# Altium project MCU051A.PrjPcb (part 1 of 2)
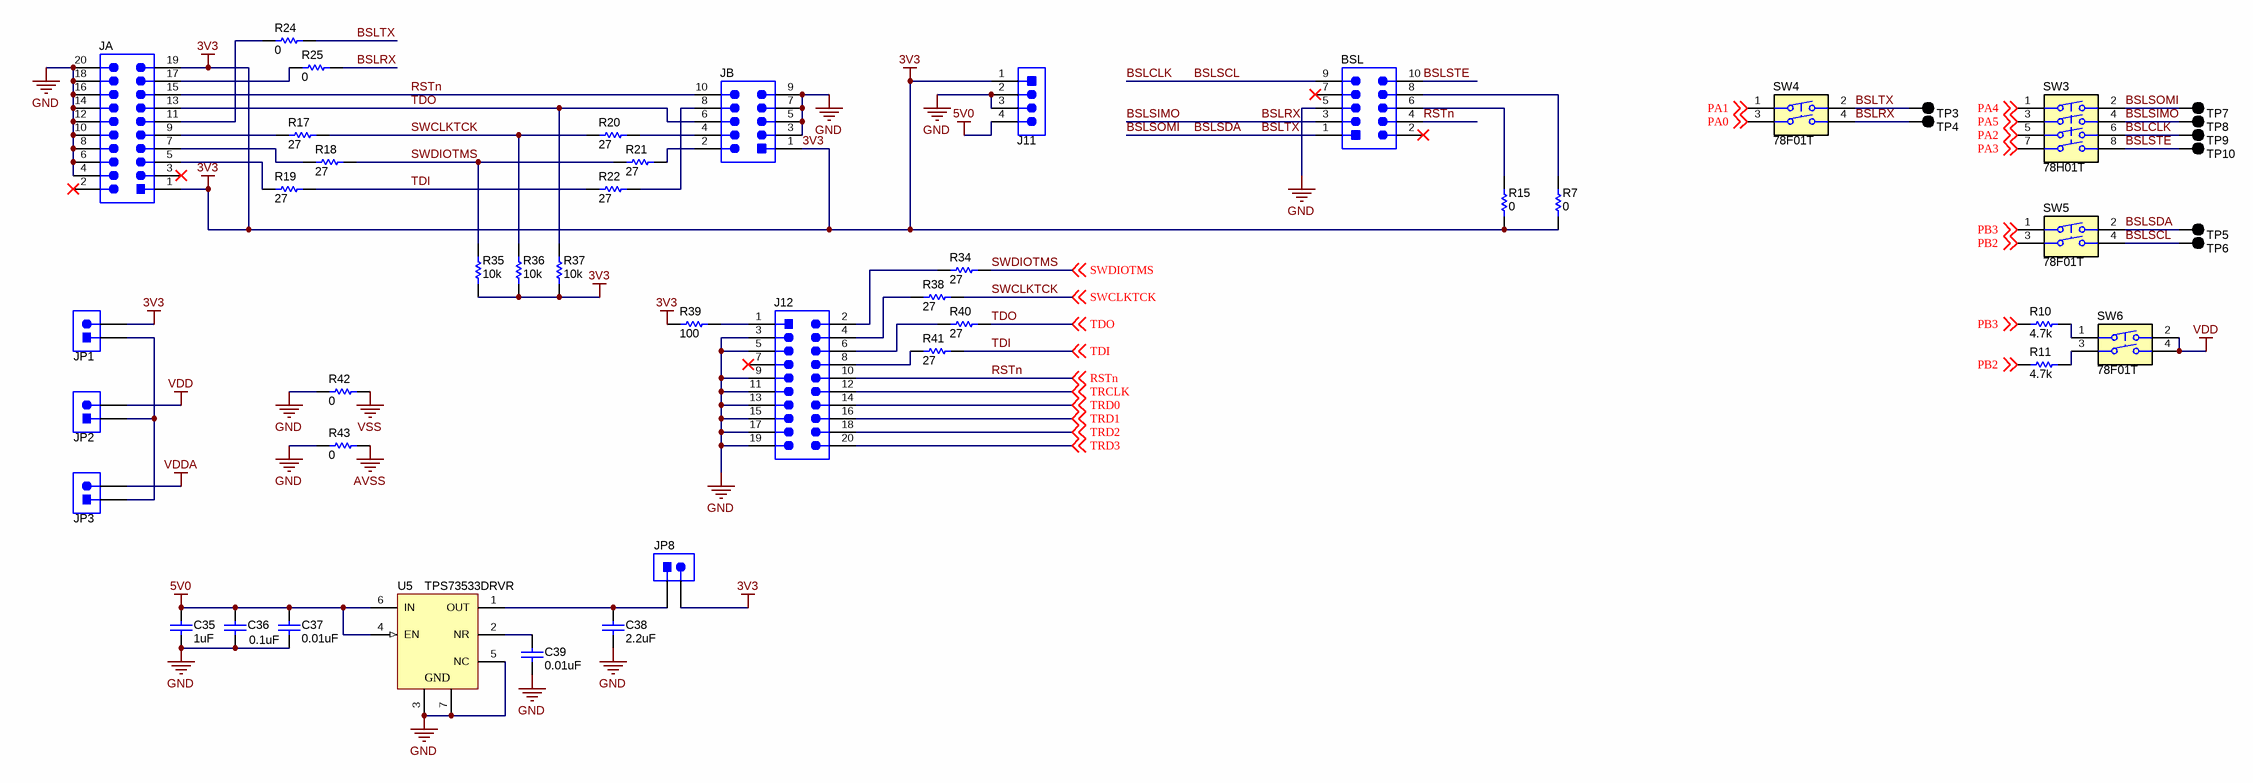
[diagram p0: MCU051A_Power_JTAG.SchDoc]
CopyrightYear: 2018; PCB_Layout: Mike Pridgen; PCB_Rev: A; PRJ_Customer: Public Release; PRJ_Engineer: Mike Pridgen; PRJ_Number: MCU051; PRJ_Title: MSP432E411Y-BGAEVM; SCH_Rev: A; TechSupport: http://www.ti.com/support; TID: N/A
4 sheets, 196 parts. Net scope: global (net labels, ports and power ports of the same name join across sheets).
Board file: MCU051A_PCB.PcbDoc
Sheets:
  MCU051A_Power_JTAG.SchDoc
  MCU051A_MSP432E_Device.SchDoc
  MCU051A_LCD_Memory.SchDoc
  MCU051A_EVM_Hardware.SchDoc

## Sheet MCU051A_Power_JTAG.SchDoc
size 431 x 279 mm; Date: Not shown in title block; ApprovedBy: Not shown in title block; CheckedBy: Not shown in title block; Author: Not shown in title block; CompanyName: Not shown in title block; Engineer: Not shown in title block; Organization: Not shown in title block; Address1: Not shown in title block; Address2: Not shown in title block; Address3: Not shown in title block; Address4: Not shown in title block; DocumentNumber: 1; Revision: Use project parameter SCH_Rev; SheetNumber: 1; SheetTotal: 4; PageSetup: Record=PageOptions¦CenterHorizontal=True¦CenterVertical=True¦PrintScale=1.00¦XCorrection=1.00¦YCorrection=1.00¦PrintKind=0¦BorderSize=5000000¦LeftOffset=0¦BottomOffset=0¦Orientation=2¦PaperLength=1000¦PaperWidth=1000¦Scale=100¦PaperSource=15¦PrintQuality=600¦MediaType=1¦DitherType=10¦PaperKind=Letter¦PrintScaleMode=1

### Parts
BSL  AWHW-10G-0202-T  [Assman_AWHW-10G-0x02-T]  (value not drawn)
C35  ValueDisplayed: 1uF  [0603]  (hidden comment: GRM188R71A105KA61D)
C36  ValueDisplayed: 0.1uF  [0603]  (hidden comment: GRM188R71C104KA01D)
C37  ValueDisplayed: 0.01uF  [0603]  (hidden comment: GRM188R71C103KA01D)
C38  ValueDisplayed: 2.2uF  [0603]  (hidden comment: GRM188Z71C225KE43)
C39  ValueDisplayed: 0.01uF  [0603]  (hidden comment: GRM188R71C103KA01D)
J11  TSW-104-07-T-S  [Samtec_TSW-104-07-T-S]  (value not drawn)
J12  FTSH-110-01-L-DV-K  [Samtec_FTSH-110-01-x-DV-K]  (value not drawn)
JA  5103309-5  [CONN_5103309-5]  (value not drawn)
JB  FTSH-105-01-F-D-K  [Samtec_FTSH-105-01-x-D-K]  (value not drawn)
JP1  HMTSW-102-07-G-S-240  [SAMTEC_HMTSW-102-07-G-S-240]  (value not drawn)
JP2  HMTSW-102-07-G-S-240  [SAMTEC_HMTSW-102-07-G-S-240]  (value not drawn)
JP3  HMTSW-102-07-G-S-240  [SAMTEC_HMTSW-102-07-G-S-240]  (value not drawn)
JP8  HMTSW-102-07-G-S-240  [SAMTEC_HMTSW-102-07-G-S-240]  (value not drawn)
R7  ValueDisplayed: 0  [0805_HV]  (hidden comment: RC0805JR-070RL)
R10  ValueDisplayed: 4.7k  [0805_HV]  (hidden comment: CRCW08054K70JNEA)
R11  ValueDisplayed: 4.7k  [0805_HV]  (hidden comment: CRCW08054K70JNEA)
R15  ValueDisplayed: 0  [0805_HV]  (hidden comment: RC0805JR-070RL)
R17  ValueDisplayed: 27  [0805_HV]  (hidden comment: CRCW080527R0JNEA)
R18  ValueDisplayed: 27  [0805_HV]  (hidden comment: CRCW080527R0JNEA)
R19  ValueDisplayed: 27  [0805_HV]  (hidden comment: CRCW080527R0JNEA)
R20  ValueDisplayed: 27  [0805_HV]  (hidden comment: CRCW080527R0JNEA)
R21  ValueDisplayed: 27  [0805_HV]  (hidden comment: CRCW080527R0JNEA)
R22  ValueDisplayed: 27  [0805_HV]  (hidden comment: CRCW080527R0JNEA)
R24  ValueDisplayed: 0  [0805_HV]  (hidden comment: RC0805JR-070RL)
R25  ValueDisplayed: 0  [0805_HV]  (hidden comment: RC0805JR-070RL)
R34  ValueDisplayed: 27  [0805_HV]  (hidden comment: CRCW080527R0JNEA)
R35  ValueDisplayed: 10k  [0603]  (hidden comment: RC1608J103CS)
R36  ValueDisplayed: 10k  [0603]  (hidden comment: RC1608J103CS)
R37  ValueDisplayed: 10k  [0603]  (hidden comment: RC1608J103CS)
R38  ValueDisplayed: 27  [0805_HV]  (hidden comment: CRCW080527R0JNEA)
R39  ValueDisplayed: 100  [0603]  (hidden comment: RC0603FR-07100RL)
R40  ValueDisplayed: 27  [0805_HV]  (hidden comment: CRCW080527R0JNEA)
R41  ValueDisplayed: 27  [0805_HV]  (hidden comment: CRCW080527R0JNEA)
R42  ValueDisplayed: 0  [0805_HV]  (hidden comment: CRCW08050000Z0EA)
R43  ValueDisplayed: 0  [0805_HV]  (hidden comment: CRCW08050000Z0EA)
SW3  78H01T  [SW_78H01T]
SW4  78F01T  [SW_78F01T]
SW5  78F01T  [SW_78F01T]
SW6  78F01T  [SW_78F01T]
TP3  5001  [Keystone5001]  (value not drawn)
TP4  5001  [Keystone5001]  (value not drawn)
TP5  5001  [Keystone5001]  (value not drawn)
TP6  5001  [Keystone5001]  (value not drawn)
TP7  5001  [Keystone5001]  (value not drawn)
TP8  5001  [Keystone5001]  (value not drawn)
TP9  5001  [Keystone5001]  (value not drawn)
TP10  5001  [Keystone5001]  (value not drawn)
U5  TPS73533DRVR  [DRV0006A]

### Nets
3V3: J11.1 JA.1 JA.19 JB.1 JP1.2 JP8.2 R7.1 R15.1 R35.1 R36.1 R37.1 R39.1
5V0: C35.1 C36.1 C37.1 J11.4 U5.4(EN) U5.6(IN)
AVSS: R43.2
GND: BSL.5 C35.2 C36.2 C37.2 C38.2 C39.2 J11.2 J11.3 J12.3 J12.5 J12.9 J12.11 J12.13 J12.15 J12.17 J12.19 JA.4 JA.6 JA.8 JA.10 JA.12 JA.14 JA.16 JA.18 JA.20 JB.3 JB.5 JB.7 JB.9 R42.1 R43.1 U5.3(GND) U5.5(NC) U5.7(GND)
VDD: JP2.2 SW6.2 SW6.4
VDDA: JP3.2
VSS: R42.2
BSLCLK: BSL.9 SW3.6 SW5.4 TP6.1 TP9.1  [also labelled BSLSCL]
BSLRX: BSL.3 R25.2 SW3.4 SW4.4 TP4.1 TP8.1  [also labelled BSLSIMO]
BSLSDA: BSL.1 R24.2 SW3.2 SW4.2 SW5.2 TP3.1 TP5.1 TP7.1  [also labelled BSLSOMI, BSLTX]
BSLSTE: BSL.10 SW3.8 TP10.1
PA0: SW4.3 ; off-sheet PA0
PA1: SW4.1 ; off-sheet PA1
PA2: SW3.5 ; off-sheet PA2
PA3: SW3.7 ; off-sheet PA3
PA4: SW3.1 ; off-sheet PA4
PA5: SW3.3 ; off-sheet PA5
PB2: R11.1 SW5.3 ; off-sheet PB2
PB3: R10.1 SW5.1 ; off-sheet PB3
RSTn: BSL.4 J12.10 JA.15 JB.10 ; off-sheet RSTn
SWCLKTCK: R17.2 R20.1 R36.2 R38.2 ; off-sheet SWCLKTCK  [project net PC0]
SWDIOTMS: R18.2 R21.1 R34.2 R35.2 ; off-sheet SWDIOTMS  [project net PC1]
TDI: R19.2 R22.1 R41.2 ; off-sheet TDI  [project net PC2]
TDO: JA.13 JB.6 R37.2 R40.2 ; off-sheet TDO  [project net PC3]
TRCLK: J12.12 ; off-sheet TRCLK  [project net PF3]
TRD0: J12.14 ; off-sheet TRD0  [project net PF2]
TRD1: J12.16 ; off-sheet TRD1  [project net PF1]
TRD2: J12.18 ; off-sheet TRD2  [project net PF0]
TRD3: J12.20 ; off-sheet TRD3  [project net PF4]
NetBSL_6: BSL.6 R15.2
NetBSL_8: BSL.8 R7.2
NetC38_1: C38.1 JP8.1 U5.1(OUT)
NetC39_1: C39.1 U5.2(NR)
NetJ12_1: J12.1 R39.2
NetJ12_2: J12.2 R34.1
NetJ12_4: J12.4 R38.1
NetJ12_6: J12.6 R40.1
NetJ12_8: J12.8 R41.1
NetJA_5: JA.5 R19.1
NetJA_7: JA.7 R18.1
NetJA_9: JA.9 R17.1
NetJA_11: JA.11 R24.1
NetJA_17: JA.17 R25.1
NetJB_2: JB.2 R21.2
NetJB_4: JB.4 R20.2
NetJB_8: JB.8 R22.2
NetJP1_1: JP1.1 JP2.1 JP3.1
NetR10_2: R10.2 SW6.1
NetR11_2: R11.2 SW6.3

Not connected (* = marked no-connect by the designer): BSL 2* 7*; J12 7*; JA 2* 3*

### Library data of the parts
BSL = CMP-0075161-1: Header(Shrouded), 2.54mm, 5x2, Gold, TH; Manufacturer: Assman WSW; CNHeader: False; Green_Lifecycle: Active; Shrouded: Y; Gender: Male; Green_REACh: Passed; Row_Count: 2; RowSpacing_mm: 2.54
C35 = CMP-0007365-4: CAP, CERM, 1 uF, 10 V, +/- 10%, X7R, 0603; Manufacturer: MuRata; TaMin_C: -55°C; ESR_ohm: 0.011; Polarized: N; SizeAreaWB_mm2: 4.68; Value1: 0.011 ohm; U/M: EA; Value: 1uF; TaMax_C: 125°C; SizeZ_mm: 1; SizeX_mm: 1.6; SizeY_mm: 0.8; Value2: 10V; SizeArea_mm2: 1.28; CompType: Capacitor; Cap_F: 1µF; AEC Category: Q200
C36 = CMP-0007378-5: CAP, CERM, 0.1 uF, 16 V, +/- 10%, X7R, 0603; Manufacturer: MuRata; TaMin_C: -55°C; Polarized: N; SizeAreaWB_mm2: 4.68; Value1: Unknown; U/M: EA; Value: 0.1uF; TaMax_C: 125°C; SizeZ_mm: 1; SizeX_mm: 1.6; SizeY_mm: 0.8; Value2: 16V; SizeArea_mm2: 1.28; CompType: Capacitor; Cap_F: 100nF; AEC Category: Q200
C37 C39 = CMP-0007377-4: CAP, CERM, 0.01 uF, 16 V, +/- 10%, X7R, 0603; Manufacturer: MuRata; TaMin_C: -55°C; Polarized: N; SizeAreaWB_mm2: 4.68; Value1: Unknown; U/M: EA; Value: 0.01uF; TaMax_C: 125°C; SizeZ_mm: 1; SizeX_mm: 1.6; Value2: 16V; SizeArea_mm2: 1.28; CompType: Capacitor; Cap_F: 10nF; AEC Category: Q200; SizeY_mm: 0.8
C38 = CMP-0007499-4: CAP, CERM, 2.2 uF, 16 V, +/- 10%, X7R, 0603; Manufacturer: MuRata; TaMin_C: -55°C; Polarized: N; SizeAreaWB_mm2: 4.68; Value1: Unknown; U/M: EA; Value: 2.2uF; TaMax_C: 125°C; SizeZ_mm: 1; SizeX_mm: 1.6; SizeY_mm: 0.8; Value2: 16V; SizeArea_mm2: 1.28; AEC Category: Q200; Cap_F: 2.2µF
J11 = CMP-0078238-2: Header, 2.54mm, 4x1, Tin, TH; Manufacturer: Samtec; Pitch_mm: 2.54; Gender: Male; Cert_UL: Y; Shrouded: N; Row_Count: 1
J12 = CMP-0075631-1: Header (Shrouded), 1.27mm, 10x2, Tin, SMT; Manufacturer: Samtec; Pitch_mm: 1.27; Gender: Male; Cert_CSA: Y; Current_A: 3.3A; CT: False; Row_Count: 2
JA = CMP-0054842-1: Header (shrouded), 100mil, 10x2,  Gold, TH; Manufacturer: TE Connectivity; CNHeader: FALSE; Green_Lifecycle: Active; Green_REACh: Passed
JB = CMP-0075533-1: Header, 1.27 mm, 5x2, Gold, TH; Manufacturer: Samtec; Pitch_mm: 1.27; Gender: Male; Green_REACh: Passed; CT: False; Shrouded: Y; Green_Lifecycle: Active; Row_Count: 2
JP1-JP3 JP8 = CMP-0075500-1: Header, 100mil, 2x1, Gold, TH; Manufacturer: Samtec; Green_REACh: Passed; CT: False; Green_Lifecycle: Active; CNHeader: True
R7 R15 R24 R25 = CMP-0020803-2: RES, 0, 5%, 0.125 W, 0805; Manufacturer: Yageo America; Power_W: 125mW; TempCo: 200 ppm/C; Value_Code: 0000; U/M: EA; Value: 0; EIA_Code: E24; SizeX_mm: 2; SizeY_mm: 1.25; SizeZ_mm: 1.45; Value2: 0.125W; SizeArea_mm2: 2.5; CompType: Resistor; VDC_V: 150V; AEC Category: Q200
R10 R11 = CMP-0020559-3: RES, 4.7 k, 5%, 0.125 W, AEC-Q200 Grade 0, 0805; Manufacturer: Vishay-Dale; Power_W: 125mW; TempCo: 200 ppm/C; Value_Code: 4k70; Value: 4.7k; EIA_Code: E24; SizeX_mm: 2; SizeY_mm: 1.25; SizeZ_mm: 1.45; Value2: 0.125W; SizeArea_mm2: 2.5; CompType: Resistor; AEC Qualified: Y; VDC_V: 150V; AEC Category: Q200; AEC Grade: 0
R17-R22 R34 R38 R40 R41 = CMP-0020509-3: RES, 27, 5%, 0.125 W, AEC-Q200 Grade 0, 0805; Manufacturer: Vishay-Dale; Power_W: 125mW; TempCo: 200 ppm/C; Value_Code: 27R0; Value: 27; EIA_Code: E24; SizeX_mm: 2; SizeY_mm: 1.25; SizeZ_mm: 1.45; Value2: 0.125W; SizeArea_mm2: 2.5; CompType: Resistor; AEC Qualified: Y; VDC_V: 150V; AEC Category: Q200; AEC Grade: 0
R35-R37 = CMP-0025945-3: RES, 10 k, 5%, 0.1 W, 0603; Manufacturer: Samsung Electro-Mechanics; Power_W: 100mW; TempCo: 100 ppm/C; Value_Code: 10k0; U/M: EA; Value: 10k; EIA_Code: E24; SizeX_mm: 1.6; SizeY_mm: 0.8; SizeZ_mm: 1; Value2: 0.1W; SizeArea_mm2: 1.28; AEC Qualified: N; VDC_V: 31V; AEC Category: Q200
R39 = CMP-0022736-2: RES, 100, 1%, 0.1 W, 0603; Manufacturer: Yageo America; Power_W: 100mW; TempCo: 200 ppm/C; Value_Code: 100R; U/M: EA; Value: 100; EIA_Code: E96; SizeX_mm: 1.6; SizeY_mm: 0.8; SizeZ_mm: 1; Value2: 0.1W; SizeArea_mm2: 1.28; VDC_V: 150V; AEC Category: Q200
R42 R43 = CMP-0020442-3: RES, 0, 5%, 0.125 W, AEC-Q200 Grade 0, 0805; Manufacturer: Vishay-Dale; Power_W: 125mW; TempCo: 200 ppm/C; Value_Code: 0000; Value: 0; EIA_Code: E24; SizeX_mm: 2; SizeY_mm: 1.25; SizeZ_mm: 1.45; Value2: 0.125W; SizeArea_mm2: 2.5; AEC Qualified: Y; VDC_V: 150V; AEC Category: Q200
SW3 = CMP-0002271-1: Switch, 4PST, Slide, Off-On, 1 Pos, 0.15A, 30V, TH; Manufacturer: Grayhill; CurrentRating_mA: 150A; PositionCount: 1
SW4-SW6 = CMP-0002270-1: Switch, DPST, Slide, Off-On, 1 Pos, 0.15A, 30V, TH; Manufacturer: Grayhill; CurrentRating_mA: 150A; PositionCount: 1
TP3-TP10 = CMP-0055138-1: Test Point, Miniature, Black, TH; Manufacturer: Keystone; CNHeader: FALSE; Green_Lifecycle: Active; Green_REACh: Passed; ContactFinish: Silver; CT: TRUE
U5 = CMP-0036330-5: Single Output High PSRR LDO, 500 mA, Fixed 3.3 V Output, 2.7 to 6.5 V Input, with Low IQ, 6-pin SON (DRV), -40 to 125 degC, Green (RoHS & no Sb/Br); Manufacturer: Texas Instruments; SubFamily: Single Channel LDO; Vin(Max)(V): 6.5; Vin(Min)(V): 2.7; Iout(Max)(A): 0.5; Iq(Typ)(mA): 0.04; Fixed Output Options(V): 3.3; Vdo(Typ)(mV): 280; Accuracy(%): 2; CompType: IC; SizeAreaWB_mm2: 9; SizeArea_mm2: 4; SizeZ_mm: 0.8

## Sheet MCU051A_MSP432E_Device.SchDoc
size 431 x 279 mm; Date: Not shown in title block; ApprovedBy: Not shown in title block; CheckedBy: Not shown in title block; Author: Not shown in title block; CompanyName: Not shown in title block; Engineer: Not shown in title block; Organization: Not shown in title block; Address1: Not shown in title block; Address2: Not shown in title block; Address3: Not shown in title block; Address4: Not shown in title block; DocumentNumber: 1; Revision: Use project parameter SCH_Rev; SheetNumber: 2; SheetTotal: 4; PageSetup: Record=PageOptions¦CenterHorizontal=True¦CenterVertical=True¦PrintScale=1.00¦XCorrection=1.00¦YCorrection=1.00¦PrintKind=0¦BorderSize=5000000¦LeftOffset=0¦BottomOffset=0¦Orientation=2¦PaperLength=1000¦PaperWidth=1000¦Scale=100¦PaperSource=15¦PrintQuality=600¦MediaType=1¦DitherType=10¦PaperKind=Letter¦PrintScaleMode=1
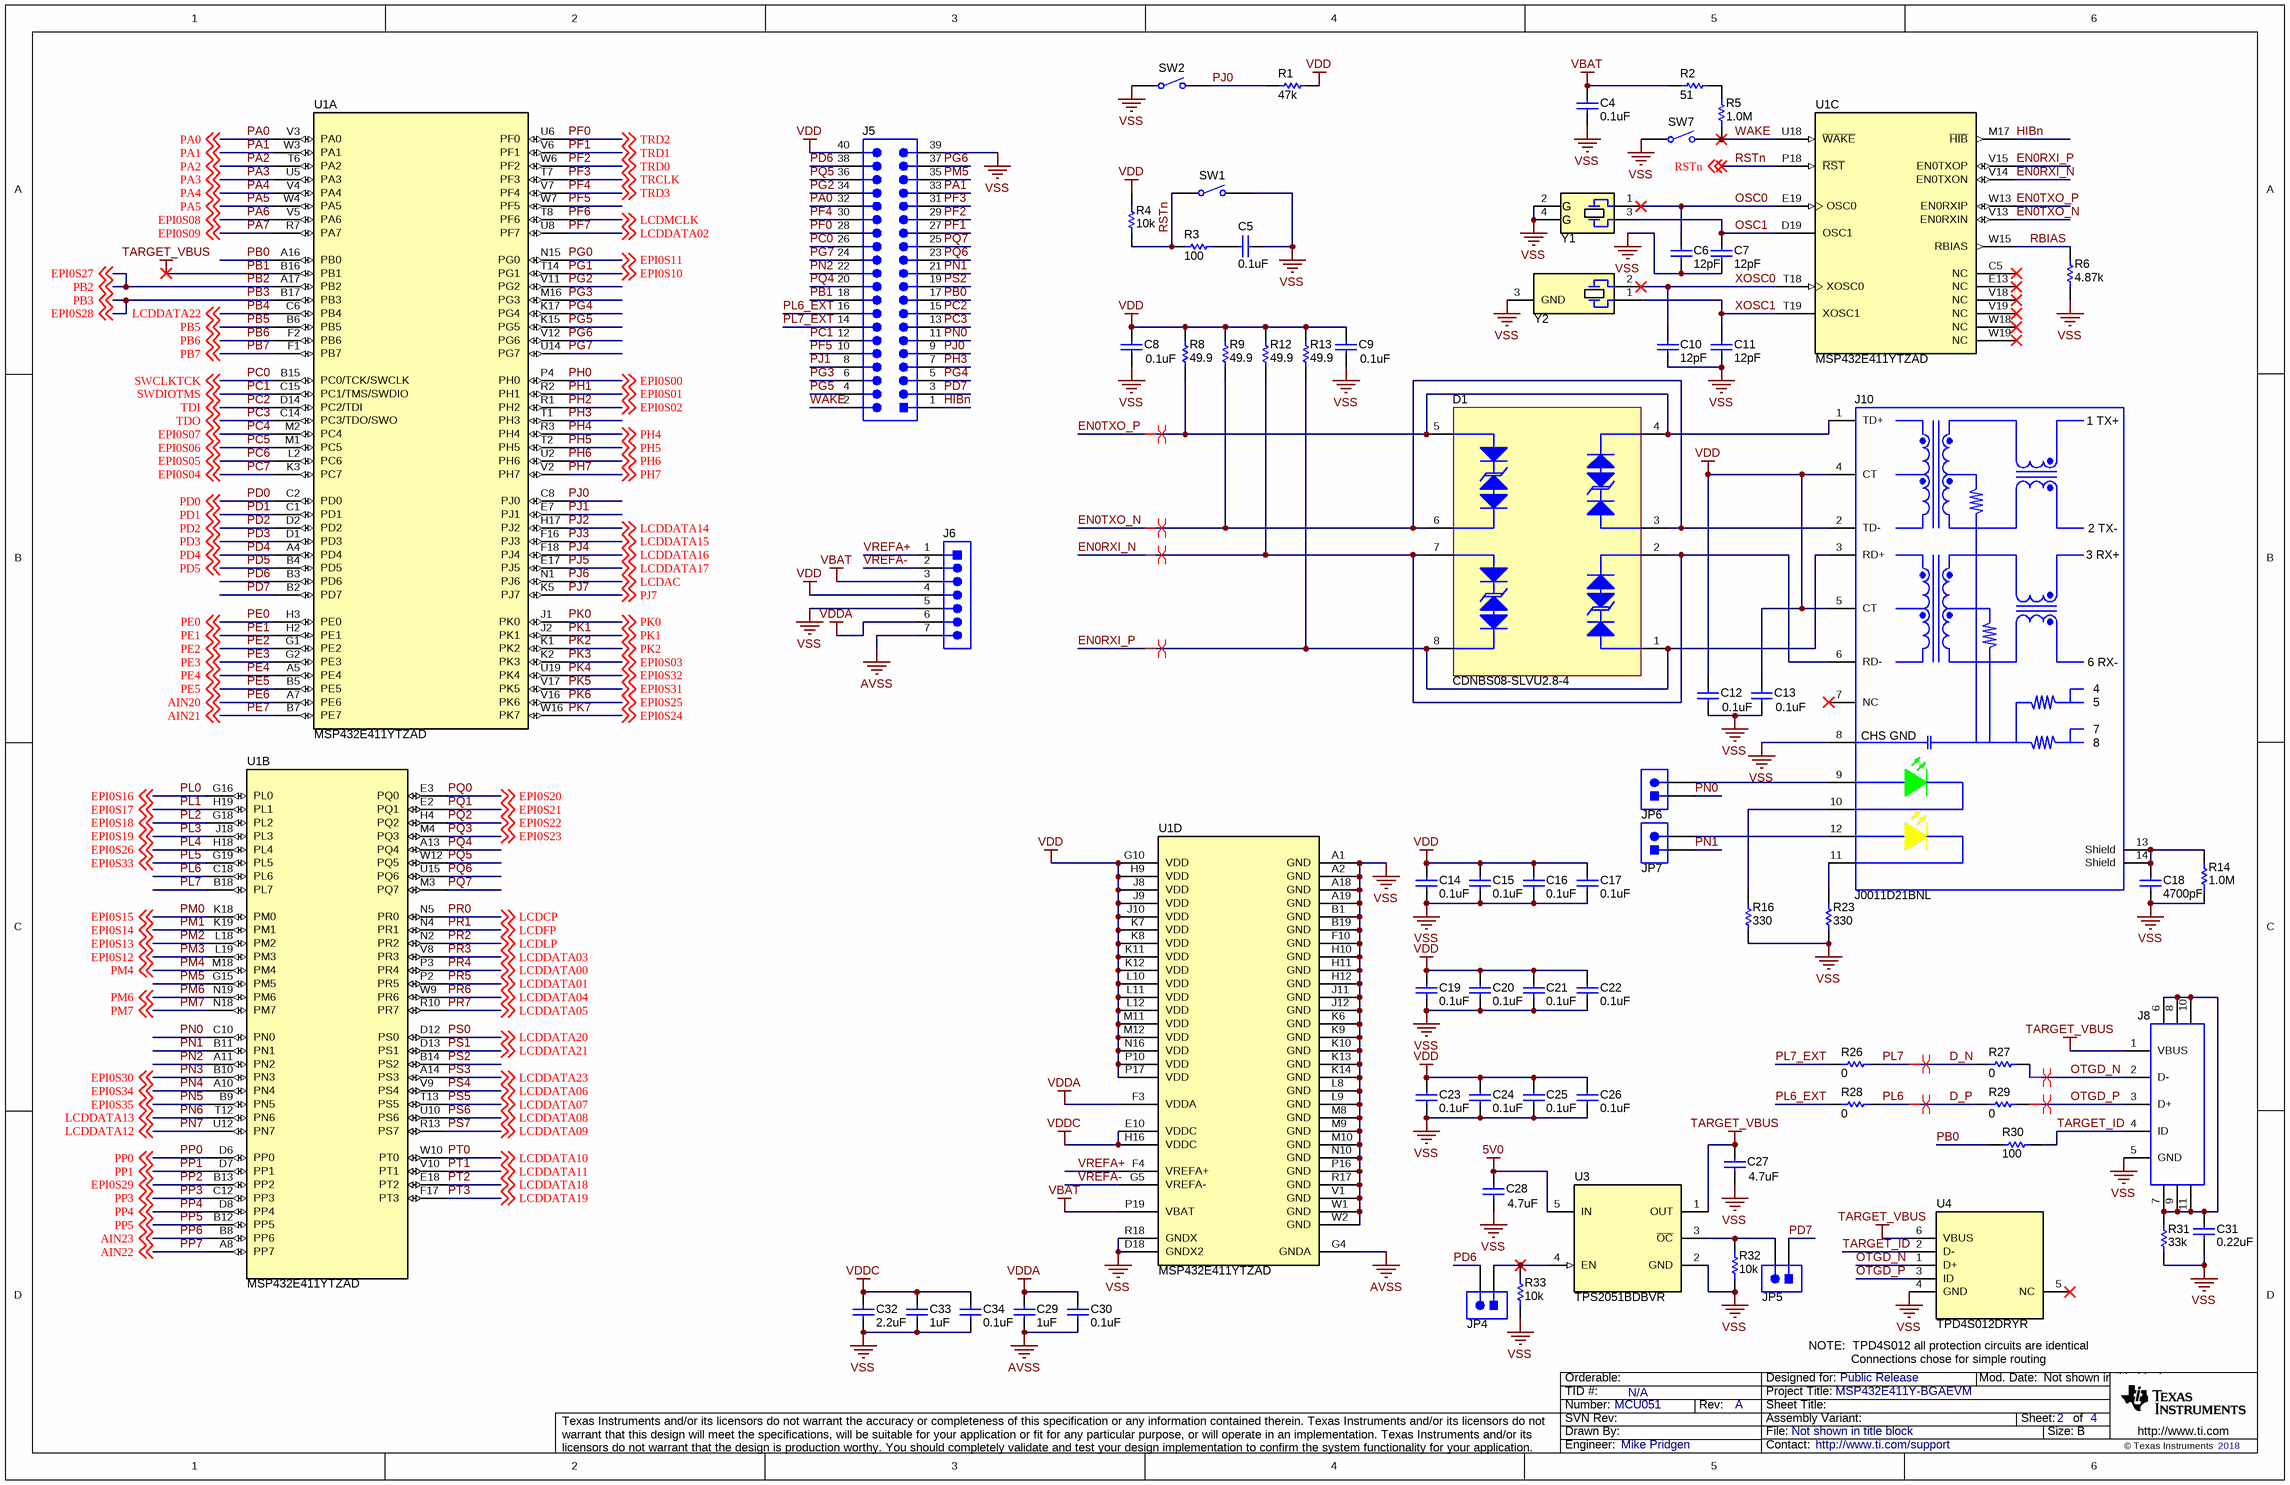
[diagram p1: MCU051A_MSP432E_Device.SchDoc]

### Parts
C4  ValueDisplayed: 0.1uF  [0603]  (hidden comment: GRM188R71C104KA01D)
C5  ValueDisplayed: 0.1uF  [0805_HV]  (hidden comment: C0805C104K4RACTU)
C6  ValueDisplayed: 12pF  [0603]  (hidden comment: GRM1885C1H120JA01D)
C7  ValueDisplayed: 12pF  [0603]  (hidden comment: GRM1885C1H120JA01D)
C8  ValueDisplayed: 0.1uF  [0603]  (hidden comment: GRM188R71C104KA01D)
C9  ValueDisplayed: 0.1uF  [0603]  (hidden comment: GRM188R71C104KA01D)
C10  ValueDisplayed: 12pF  [0603]  (hidden comment: GRM1885C1H120JA01D)
C11  ValueDisplayed: 12pF  [0603]  (hidden comment: GRM1885C1H120JA01D)
C12  ValueDisplayed: 0.1uF  [0603]  (hidden comment: GRM188R71C104KA01D)
C13  ValueDisplayed: 0.1uF  [0603]  (hidden comment: GRM188R71C104KA01D)
C14  ValueDisplayed: 0.1uF  [0402]  (hidden comment: GRM155R71A104KA01D)
C15  ValueDisplayed: 0.1uF  [0402]  (hidden comment: GRM155R71A104KA01D)
C16  ValueDisplayed: 0.1uF  [0402]  (hidden comment: GRM155R71A104KA01D)
C17  ValueDisplayed: 0.1uF  [0402]  (hidden comment: GRM155R71A104KA01D)
C18  ValueDisplayed: 4700pF  [0603]  (hidden comment: 06031C472KAT2A)
C19  ValueDisplayed: 0.1uF  [0402]  (hidden comment: GRM155R71A104KA01D)
C20  ValueDisplayed: 0.1uF  [0402]  (hidden comment: GRM155R71A104KA01D)
C21  ValueDisplayed: 0.1uF  [0402]  (hidden comment: GRM155R71A104KA01D)
C22  ValueDisplayed: 0.1uF  [0402]  (hidden comment: GRM155R71A104KA01D)
C23  ValueDisplayed: 0.1uF  [0402]  (hidden comment: GRM155R71A104KA01D)
C24  ValueDisplayed: 0.1uF  [0402]  (hidden comment: GRM155R71A104KA01D)
C25  ValueDisplayed: 0.1uF  [0402]  (hidden comment: GRM155R71A104KA01D)
C26  ValueDisplayed: 0.1uF  [0402]  (hidden comment: GRM155R71A104KA01D)
C27  ValueDisplayed: 4.7uF  [0805_HV]  (hidden comment: 885012207025)
C28  ValueDisplayed: 4.7uF  [0805_HV]  (hidden comment: 885012207025)
C29  ValueDisplayed: 1uF  [0402]  (hidden comment: GRM155R70J105KA12D)
C30  ValueDisplayed: 0.1uF  [0402]  (hidden comment: GRM155R71A104KA01D)
C31  ValueDisplayed: 0.22uF  [0603]  (hidden comment: GRM188R71H224KAC4D)
C32  ValueDisplayed: 2.2uF  [0603]  (hidden comment: GRM188Z71C225KE43)
C33  ValueDisplayed: 1uF  [0402]  (hidden comment: GRM155R70J105KA12D)
C34  ValueDisplayed: 0.1uF  [0402]  (hidden comment: GRM155R71A104KA01D)
D1  CDNBS08-SLVU2.8-4  [SOIC-8]
J5  TSW-120-07-G-D  [TSW-120-07-G-D]  (value not drawn)
J6  TSW-107-07-G-S  [TSW-107-XX-XXX-S]  (value not drawn)
J8  ZX62D-AB-5P8(30)  [Hirose-ZX62D-AB-5P8]  (value not drawn)
J10  J0011D21BNL  [Pulse_J0011D21BNL]
JP4  HMTSW-102-07-G-S-240  [SAMTEC_HMTSW-102-07-G-S-240]  (value not drawn)
JP5  HMTSW-102-07-G-S-240  [SAMTEC_HMTSW-102-07-G-S-240]  (value not drawn)
JP6  HMTSW-102-07-G-S-240  [SAMTEC_HMTSW-102-07-G-S-240]  (value not drawn)
JP7  HMTSW-102-07-G-S-240  [SAMTEC_HMTSW-102-07-G-S-240]  (value not drawn)
R1  ValueDisplayed: 47k  [0603]  (hidden comment: RC0603JR-0747KL)
R2  ValueDisplayed: 51  [0603]  (hidden comment: CRCW060351R0JNEA)
R3  ValueDisplayed: 100  [0805_HV]  (hidden comment: CRCW0805100RJNEA)
R4  ValueDisplayed: 10k  [0805_HV]  (hidden comment: CRCW080510K0JNEA)
R5  ValueDisplayed: 1.0M  [0603]  (hidden comment: CRCW06031M00JNEA)
R6  ValueDisplayed: 4.87k  [0603]  (hidden comment: RC0603FR-074K87L)
R8  ValueDisplayed: 49.9  [0603]  (hidden comment: RC0603FR-0749R9L)
R9  ValueDisplayed: 49.9  [0603]  (hidden comment: RC0603FR-0749R9L)
R12  ValueDisplayed: 49.9  [0603]  (hidden comment: RC0603FR-0749R9L)
R13  ValueDisplayed: 49.9  [0603]  (hidden comment: RC0603FR-0749R9L)
R14  ValueDisplayed: 1.0M  [0603]  (hidden comment: CRCW06031M00JNEA)
R16  ValueDisplayed: 330  [0603]  (hidden comment: RC0603JR-07330RL)
R23  ValueDisplayed: 330  [0603]  (hidden comment: RC0603JR-07330RL)
R26  ValueDisplayed: 0  [0603]  (hidden comment: CRCW06030000Z0EA)
R27  ValueDisplayed: 0  [0603]  (hidden comment: CRCW06030000Z0EA)
R28  ValueDisplayed: 0  [0603]  (hidden comment: CRCW06030000Z0EA)
R29  ValueDisplayed: 0  [0603]  (hidden comment: CRCW06030000Z0EA)
R30  ValueDisplayed: 100  [0603]  (hidden comment: CRCW0603100RJNEA)
R31  ValueDisplayed: 33k  [0603]  (hidden comment: RC0603JR-0733KL)
R32  ValueDisplayed: 10k  [0805_HV]  (hidden comment: CRCW080510K0JNEA)
R33  ValueDisplayed: 10k  [0805_HV]  (hidden comment: CRCW080510K0JNEA)
SW1  EVQ-11A04M  [SW_EVQ11_04]  (value not drawn)
SW2  EVQ-11A04M  [SW_EVQ11_04]  (value not drawn)
SW7  EVQ-11A04M  [SW_EVQ11_04]  (value not drawn)
U1  MSP432E411YTZAD  [ZAD0212A]  (parts A,B,C,D of 4)
U3  TPS2051BDBVR  [DBV0005A_N]
U4  TPD4S012DRYR  [DRY0006A]
Y1  603-25-261  [NDK_NX3225GA]  (value not drawn)
Y2  CMR200T-32.768KDZY-UT  [CFM_CMR200T]  (value not drawn)

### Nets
5V0: C28.1 U3.5(IN)
AVSS: C29.1 C30.1 J6.7 U1.G4(GNDA)
PB1: C27.1 J5.18 J8.1(VBUS) U1.B16(PB1) U3.1(OUT) U4.6(VBUS)  [also labelled TARGET_VBUS]
VBAT: C4.1 J6.3 R2.1 U1.P19(VBAT)
VDD: C8.1 C9.1 C12.1 C13.1 C14.2 C15.2 C16.2 C17.2 C19.2 C20.2 C21.2 C22.2 C23.2 C24.2 C25.2 C26.2 J5.40 J6.4 J10.4(CT) J10.5(CT) R1.2 R4.2 R8.2 R9.2 R12.2 R13.2 U1.G10(VDD) U1.H9(VDD) U1.J8(VDD) U1.J9(VDD) U1.J10(VDD) U1.K7(VDD) U1.K8(VDD) U1.K11(VDD) U1.K12(VDD) U1.L10(VDD) U1.L11(VDD) U1.L12(VDD) U1.M11(VDD) U1.M12(VDD) U1.N16(VDD) U1.P10(VDD) U1.P17(VDD)
VDDA: C29.2 C30.2 J6.6 U1.F3(VDDA)
VDDC: C32.1 C33.2 C34.2 U1.E10(VDDC) U1.H16(VDDC)
VSS: C4.2 C5.1 C6.1 C7.1 C8.2 C9.2 C10.1 C11.1 C12.2 C13.2 C14.1 C15.1 C16.1 C17.1 C18.2 C19.1 C20.1 C21.1 C22.1 C23.1 C24.1 C25.1 C26.1 C27.2 C28.2 C31.2 C32.2 C33.1 C34.1 J5.39 J6.5 J8.5(GND) J10.8(CHS_GND) R6.1 R14.1 R16.1 R23.1 R31.1 R32.2 R33.1 SW1.2 SW2.1 SW7.1 U1.A1(GND) U1.A2(GND) U1.A18(GND) U1.A19(GND) U1.B1(GND) U1.B19(GND) U1.D18(GNDX2) U1.F10(GND) U1.H10(GND) U1.H11(GND) U1.H12(GND) U1.J11(GND) U1.J12(GND) U1.K6(GND) U1.K9(GND) U1.K10(GND) U1.K13(GND) U1.K14(GND) U1.L8(GND) U1.L9(GND) U1.M8(GND) U1.M9(GND) U1.M10(GND) U1.N10(GND) U1.P16(GND) U1.R17(GND) U1.R18(GNDX) U1.V1(GND) U1.W1(GND) U1.W2(GND) U3.2(GND) U4.4(GND) Y1.2(GND) Y1.4(GND) Y2.3(GND)
D_N: R26.2 R27.1 U1.B18(PL7)  [also labelled PL7]
D_P: R28.2 R29.1 U1.C18(PL6)  [also labelled PL6]
EN0RXI_N: D1.2 D1.7 J10.6(RD-) R12.1 U1.V14(EN0TXON)
EN0RXI_P: D1.1 D1.8 J10.3(RD+) R13.1 U1.V15(EN0TXOP)
EN0TXO_N: D1.3 D1.6 J10.2(TD-) R9.1 U1.V13(EN0RXIN)
EN0TXO_P: D1.4 D1.5 J10.1(TD+) R8.1 U1.W13(EN0RXIP)
HIBn: J5.1 U1.M17(~{HIB})
OSC0: C6.2 U1.E19(OSC0) Y1.1
OSC1: C7.2 U1.D19(OSC1) Y1.3
OTGD_N: J8.2(D-) R27.2 U4.1(D+)
OTGD_P: J8.3(D+) R29.2 U4.3(ID)
PA0: J5.32 U1.V3(PA0) ; off-sheet PA0
PA1: J5.33 U1.W3(PA1) ; off-sheet PA1
PA2: U1.T6(PA2) ; off-sheet PA2
PA3: U1.U5(PA3) ; off-sheet PA3
PA4: U1.V4(PA4) ; off-sheet PA4
PA5: U1.W4(PA5) ; off-sheet PA5
PA6: U1.V5(PA6) ; off-sheet EPI0S08  [also labelled EPI0S08]
PA7: U1.R7(PA7) ; off-sheet EPI0S09  [also labelled EPI0S09]
PB0: J5.17 R30.1 U1.A16(PB0)
PB2: U1.A17(PB2) ; off-sheet PB2, off-sheet EPI0S27  [also labelled EPI0S27]
PB3: U1.B17(PB3) ; off-sheet PB3, off-sheet EPI0S28  [also labelled EPI0S28]
PB4: U1.C6(PB4) ; off-sheet LCDDATA22  [also labelled LCDDATA22]
PB5: U1.B6(PB5) ; off-sheet PB5
PB6: U1.F2(PB6) ; off-sheet PB6
PB7: U1.F1(PB7) ; off-sheet PB7
PC0: J5.26 U1.B15(PC0/TCK/SWCLK) ; off-sheet SWCLKTCK  [also labelled SWCLKTCK]
PC1: J5.12 U1.C15(PC1/TMS/SWDIO) ; off-sheet SWDIOTMS  [also labelled SWDIOTMS]
PC2: J5.15 U1.D14(PC2/TDI) ; off-sheet TDI  [also labelled TDI]
PC3: J5.13 U1.C14(PC3/TDO/SWO) ; off-sheet TDO  [also labelled TDO]
PC4: U1.M2(PC4) ; off-sheet EPI0S07  [also labelled EPI0S07]
PC5: U1.M1(PC5) ; off-sheet EPI0S06  [also labelled EPI0S06]
PC6: U1.L2(PC6) ; off-sheet EPI0S05  [also labelled EPI0S05]
PC7: U1.K3(PC7) ; off-sheet EPI0S04  [also labelled EPI0S04]
PD0: U1.C2(PD0) ; off-sheet PD0
PD1: U1.C1(PD1) ; off-sheet PD1
PD2: U1.D2(PD2) ; off-sheet PD2
PD3: U1.D1(PD3) ; off-sheet PD3
PD4: U1.A4(PD4) ; off-sheet PD4
PD5: U1.B4(PD5) ; off-sheet PD5
PD6: J5.38 JP4.2 U1.B3(PD6)
PD7: J5.3 JP5.1 U1.B2(PD7)
PE0: U1.H3(PE0) ; off-sheet PE0
PE1: U1.H2(PE1) ; off-sheet PE1
PE2: U1.G1(PE2) ; off-sheet PE2
PE3: U1.G2(PE3) ; off-sheet PE3
PE4: U1.A5(PE4) ; off-sheet PE4
PE5: U1.B5(PE5) ; off-sheet PE5
PE6: U1.A7(PE6) ; off-sheet AIN20  [also labelled AIN20]
PE7: U1.B7(PE7) ; off-sheet AIN21  [also labelled AIN21]
PF0: J5.28 U1.U6(PF0) ; off-sheet TRD2  [also labelled TRD2]
PF1: J5.27 U1.V6(PF1) ; off-sheet TRD1  [also labelled TRD1]
PF2: J5.29 U1.W6(PF2) ; off-sheet TRD0  [also labelled TRD0]
PF3: J5.31 U1.T7(PF3) ; off-sheet TRCLK  [also labelled TRCLK]
PF4: J5.30 U1.V7(PF4) ; off-sheet TRD3  [also labelled TRD3]
PF5: J5.10 U1.W7(PF5)
PF6: U1.T8(PF6) ; off-sheet LCDMCLK  [also labelled LCDMCLK]
PF7: U1.U8(PF7) ; off-sheet LCDDATA02  [also labelled LCDDATA02]
PG0: U1.N15(PG0) ; off-sheet EPI0S11  [also labelled EPI0S11]
PG1: U1.T14(PG1) ; off-sheet EPI0S10  [also labelled EPI0S10]
PG2: J5.34 U1.V11(PG2)
PG3: J5.6 U1.M16(PG3)
PG4: J5.5 U1.K17(PG4)
PG5: J5.4 U1.K15(PG5)
PG6: J5.37 U1.V12(PG6)
PG7: J5.24 U1.U14(PG7)
PH0: U1.P4(PH0) ; off-sheet EPI0S00  [also labelled EPI0S00]
PH1: U1.R2(PH1) ; off-sheet EPI0S01  [also labelled EPI0S01]
PH2: U1.R1(PH2) ; off-sheet EPI0S02  [also labelled EPI0S02]
PH3: J5.7 U1.T1(PH3)
PH4: U1.R3(PH4) ; off-sheet PH4
PH5: U1.T2(PH5) ; off-sheet PH5
PH6: U1.U2(PH6) ; off-sheet PH6
PH7: U1.V2(PH7) ; off-sheet PH7
PJ0: J5.9 R1.1 SW2.2 U1.C8(PJ0)
PJ1: J5.8 U1.E7(PJ1)
PJ2: U1.H17(PJ2) ; off-sheet LCDDATA14  [also labelled LCDDATA14]
PJ3: U1.F16(PJ3) ; off-sheet LCDDATA15  [also labelled LCDDATA15]
PJ4: U1.F18(PJ4) ; off-sheet LCDDATA16  [also labelled LCDDATA16]
PJ5: U1.E17(PJ5) ; off-sheet LCDDATA17  [also labelled LCDDATA17]
PJ6: U1.N1(PJ6) ; off-sheet LCDAC  [also labelled LCDAC]
PJ7: U1.K5(PJ7) ; off-sheet PJ7
PK0: U1.J1(PK0) ; off-sheet PK0
PK1: U1.J2(PK1) ; off-sheet PK1
PK2: U1.K1(PK2) ; off-sheet PK2
PK3: U1.K2(PK3) ; off-sheet EPI0S03  [also labelled EPI0S03]
PK4: U1.U19(PK4) ; off-sheet EPI0S32  [also labelled EPI0S32]
PK5: U1.V17(PK5) ; off-sheet EPI0S31  [also labelled EPI0S31]
PK6: U1.V16(PK6) ; off-sheet EPI0S25  [also labelled EPI0S25]
PK7: U1.W16(PK7) ; off-sheet EPI0S24  [also labelled EPI0S24]
PL0: U1.G16(PL0) ; off-sheet EPI0S16  [also labelled EPI0S16]
PL1: U1.H19(PL1) ; off-sheet EPI0S17  [also labelled EPI0S17]
PL2: U1.G18(PL2) ; off-sheet EPI0S18  [also labelled EPI0S18]
PL3: U1.J18(PL3) ; off-sheet EPI0S19  [also labelled EPI0S19]
PL4: U1.H18(PL4) ; off-sheet EPI0S26  [also labelled EPI0S26]
PL5: U1.G19(PL5) ; off-sheet EPI0S33  [also labelled EPI0S33]
PL6_EXT: J5.16 R28.1
PL7_EXT: J5.14 R26.1
PM0: U1.K18(PM0) ; off-sheet EPI0S15  [also labelled EPI0S15]
PM1: U1.K19(PM1) ; off-sheet EPI0S14  [also labelled EPI0S14]
PM2: U1.L18(PM2) ; off-sheet EPI0S13  [also labelled EPI0S13]
PM3: U1.L19(PM3) ; off-sheet EPI0S12  [also labelled EPI0S12]
PM4: U1.M18(PM4) ; off-sheet PM4
PM5: J5.35 U1.G15(PM5)
PM6: U1.N19(PM6) ; off-sheet PM6
PM7: U1.N18(PM7) ; off-sheet PM7
PN0: J5.11 JP6.1 U1.C10(PN0)
PN1: J5.21 JP7.1 U1.B11(PN1)
PN2: J5.22 U1.A11(PN2)
PN3: U1.B10(PN3) ; off-sheet EPI0S30  [also labelled EPI0S30]
PN4: U1.A10(PN4) ; off-sheet EPI0S34  [also labelled EPI0S34]
PN5: U1.B9(PN5) ; off-sheet EPI0S35  [also labelled EPI0S35]
PN6: U1.T12(PN6) ; off-sheet LCDDATA13  [also labelled LCDDATA13]
PN7: U1.U12(PN7) ; off-sheet LCDDATA12  [also labelled LCDDATA12]
PP0: U1.D6(PP0) ; off-sheet PP0
PP1: U1.D7(PP1) ; off-sheet PP1
PP2: U1.B13(PP2) ; off-sheet EPI0S29  [also labelled EPI0S29]
PP3: U1.C12(PP3) ; off-sheet PP3
PP4: U1.D8(PP4) ; off-sheet PP4
PP5: U1.B12(PP5) ; off-sheet PP5
PP6: U1.B8(PP6) ; off-sheet AIN23  [also labelled AIN23]
PP7: U1.A8(PP7) ; off-sheet AIN22  [also labelled AIN22]
PQ0: U1.E3(PQ0) ; off-sheet EPI0S20  [also labelled EPI0S20]
PQ1: U1.E2(PQ1) ; off-sheet EPI0S21  [also labelled EPI0S21]
PQ2: U1.H4(PQ2) ; off-sheet EPI0S22  [also labelled EPI0S22]
PQ3: U1.M4(PQ3) ; off-sheet EPI0S23  [also labelled EPI0S23]
PQ4: J5.20 U1.A13(PQ4)
PQ5: J5.36 U1.W12(PQ5)
PQ6: J5.23 U1.U15(PQ6)
PQ7: J5.25 U1.M3(PQ7)
PR0: U1.N5(PR0) ; off-sheet LCDCP  [also labelled LCDCP]
PR1: U1.N4(PR1) ; off-sheet LCDFP  [also labelled LCDFP]
PR2: U1.N2(PR2) ; off-sheet LCDLP  [also labelled LCDLP]
PR3: U1.V8(PR3) ; off-sheet LCDDATA03  [also labelled LCDDATA03]
PR4: U1.P3(PR4) ; off-sheet LCDDATA00  [also labelled LCDDATA00]
PR5: U1.P2(PR5) ; off-sheet LCDDATA01  [also labelled LCDDATA01]
PR6: U1.W9(PR6) ; off-sheet LCDDATA04  [also labelled LCDDATA04]
PR7: U1.R10(PR7) ; off-sheet LCDDATA05  [also labelled LCDDATA05]
PS0: U1.D12(PS0) ; off-sheet LCDDATA20  [also labelled LCDDATA20]
PS1: U1.D13(PS1) ; off-sheet LCDDATA21  [also labelled LCDDATA21]
PS2: J5.19 U1.B14(PS2)
PS3: U1.A14(PS3) ; off-sheet LCDDATA23  [also labelled LCDDATA23]
PS4: U1.V9(PS4) ; off-sheet LCDDATA06  [also labelled LCDDATA06]
PS5: U1.T13(PS5) ; off-sheet LCDDATA07  [also labelled LCDDATA07]
PS6: U1.U10(PS6) ; off-sheet LCDDATA08  [also labelled LCDDATA08]
PS7: U1.R13(PS7) ; off-sheet LCDDATA09  [also labelled LCDDATA09]
PT0: U1.W10(PT0) ; off-sheet LCDDATA10  [also labelled LCDDATA10]
PT1: U1.V10(PT1) ; off-sheet LCDDATA11  [also labelled LCDDATA11]
PT2: U1.E18(PT2) ; off-sheet LCDDATA18  [also labelled LCDDATA18]
PT3: U1.F17(PT3) ; off-sheet LCDDATA19  [also labelled LCDDATA19]
RBIAS: R6.2 U1.W15(RBIAS)
RSTn: R3.1 R4.1 SW1.1 U1.P18(~{RST}) ; off-sheet RSTn
TARGET_ID: J8.4(ID) R30.2 U4.2(D-)
VREFA+: J6.1 U1.F4(VREFA+)
VREFA-: J6.2 U1.G5(VREFA-)
WAKE: J5.2 R5.1 SW7.2 U1.U18(~{WAKE})
XOSC0: C10.2 U1.T18(XOSC0) Y2.2
XOSC1: C11.2 U1.T19(XOSC1) Y2.1
NetC5_2: C5.2 R3.2
NetC18_1: C18.1 J10.13(Shield) J10.14(Shield) R14.2
NetC31_1: C31.1 J8.6 J8.7 J8.8 J8.9 J8.10 J8.11 R31.2
NetJ10_9: J10.9(LEFT_LED_ANODE) JP6.2
NetJ10_10: J10.10(LEFT_LED) R16.2
NetJ10_11: J10.11(RIGHT_LED_ANODE) R23.2
NetJ10_12: J10.12(RIGHT_LED) JP7.2
NetJP4_1: JP4.1 R33.2 U3.4(EN)
NetJP5_2: JP5.2 R32.1 U3.3(~{OC})
NetR2_2: R2.2 R5.2

Not connected (* = marked no-connect by the designer): J10 7(NC)*; U1 C5(NC)* E13(NC)* V18(NC)* V19(NC)* W18(NC)* W19(NC)*; U4 5(NC)*

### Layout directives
differential pair: D_N, D_P, EN0RXI_N, EN0RXI_P, EN0TXO_N, EN0TXO_P, OTGD_N, OTGD_P

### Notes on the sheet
- NOTE:  TPD4S012 all protection circuits are identical
- Connections chose for simple routing

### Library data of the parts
C4 C8 C9 C12 C13 = CMP-0007378-5: as C36 on sheet MCU051A_Power_JTAG
C5 = CMP-0007724-2: CAP, CERM, 0.1 uF, 16 V, +/- 10%, X7R, 0805; Manufacturer: Kemet; TaMin_C: -55°C; ESR_ohm: 0.064; Polarized: N; SizeAreaWB_mm2: 6.75; Value1: 0.064 ohm; U/M: EA; Value: 0.1uF; TaMax_C: 125°C; SizeZ_mm: 1.45; SizeX_mm: 2; SizeY_mm: 1.25; Cap_Case: 0805; SizeArea_mm2: 2.5; CompType: Capacitor; Cap_F: 100nF; VDC_V: 16V; IRMS_A: 1.64A; AEC Category: Q200
C6 C7 C10 C11 = CMP-0007178-4: CAP, CERM, 12 pF, 50 V, +/- 5%, C0G/NP0, 0603; Manufacturer: MuRata; TaMin_C: -55°C; Polarized: N; SizeAreaWB_mm2: 4.68; Value1: Unknown; U/M: EA; Value: 12pF; TaMax_C: 125°C; SizeZ_mm: 1; SizeX_mm: 1.6; SizeY_mm: 0.8; Value2: 50V; SizeArea_mm2: 1.28; CompType: Capacitor; AEC Category: Q200
C14-C17 C19-C26 C30 C34 = CMP-0006629-2: CAP, CERM, 0.1 uF, 10 V, +/- 10%, X7R, 0402; Manufacturer: MuRata; TaMin_C: -55°C; Polarized: N; SizeAreaWB_mm2: 3; Value1: Unknown; U/M: EA; Value: 0.1uF; TaMax_C: 125°C; SizeZ_mm: 0.6; SizeX_mm: 1; SizeY_mm: 0.5; Value2: 10V; CompType: Capacitor; Cap_F: 100nF; AEC Category: Q200
C18 = CMP-0006746-5: CAP, CERM, 4700 pF, 100 V, +/- 10%, X7R, 0603; Manufacturer: AVX; TaMin_C: -55°C; ESR_ohm: 1.36d; Polarized: N; SizeAreaWB_mm2: 4.68; Value1: 0.136 ohm; U/M: EA; Value: 4700pF; TaMax_C: 125°C; SizeZ_mm: 1; SizeX_mm: 1.6; SizeY_mm: 0.8; Value2: 100V; SizeArea_mm2: 1.28; CompType: Capacitor; Cap_F: 4.7nF; AEC Category: Q200
C27 C28 = CMP-0007690-2: CAP, CERM, 4.7 uF, 10 V, +/- 10%, X7R, 0805; Manufacturer: Wurth Elektronik; TaMin_C: -55°C; Polarized: N; SizeAreaWB_mm2: 6.75; Value1: Unknown; U/M: EA; Value: 4.7uF; TaMax_C: 125°C; SizeZ_mm: 1.45; SizeX_mm: 2; SizeY_mm: 1.25; Cap_Case: 0805; Value2: 10V; SizeArea_mm2: 2.5; CompType: Capacitor; Cap_F: 4.7µF; AEC Category: Q200
C29 C33 = CMP-0064947-2: CAP, CERM, 1 uF, 6.3 V,+/- 10%, X7R, 0402; Manufacturer: MuRata; TaMin_C: -55°C; Polarized: N; SizeAreaWB_mm2: 3; Value1: Unknown; U/M: EA; Value: 1uF; TaMax_C: 125°C; SizeZ_mm: 0.6; SizeX_mm: 1; SizeY_mm: 0.5; Value2: 6.3V; CompType: Capacitor; Cap_F: 1µF; AEC Category: Q200
C31 = CMP-0007445-4: CAP, CERM, 0.22 uF, 50 V, +/- 10%, X7R, 0603; Manufacturer: MuRata; TaMin_C: -55°C; Polarized: N; SizeAreaWB_mm2: 4.68; Value1: Unknown; U/M: EA; Value: 0.22uF; TaMax_C: 125°C; SizeZ_mm: 1; SizeX_mm: 1.6; SizeY_mm: 0.8; Value2: 50V; SizeArea_mm2: 1.28; CompType: Capacitor; Cap_F: 220nF; AEC Category: Q200
C32 = CMP-0007499-4: CAP, CERM, 2.2 uF, 16 V, +/- 10%, X7R, 0603; Manufacturer: MuRata; TaMin_C: -55°C; Polarized: N; SizeAreaWB_mm2: 4.68; Value1: Unknown; U/M: EA; Value: 2.2uF; TaMax_C: 125°C; SizeZ_mm: 1; SizeX_mm: 1.6; SizeY_mm: 0.8; Value2: 16V; SizeArea_mm2: 1.28; CompType: Capacitor; AEC Category: Q200; Cap_F: 2.2µF
D1 = CMP-0082307-1: Low Capacitance TVS Array, 2.8V, SOIC-8; Manufacturer: Bourns; SizeAreaWB_mm2: 55.131; SizeArea_mm2: 29.351; SizeZ_mm: 1.75; SizeY_mm: 4.9; SizeX_mm: 5.99
J5 = CMP-0075433-1: Header, 100mil, 20x2, Gold, TH; Manufacturer: Samtec; Pitch_mm: 2.54; Cert_VDE: N; Gender: Male; Cert_CSA: Y; Voltage_V: 550V; Green_REACh: Passed; Current_A: 6.3A; CT: False; Green_Lifecycle: Active; Row_Count: 2; CNHeader: True
J6 = CMP-0075416-1: Header, 100mil, 7x1, Gold, TH; Manufacturer: Samtec; Pitch_mm: 2.54; Cert_VDE: N; Gender: Male; Cert_CSA: Y; Voltage_V: 550V; Green_REACh: Passed; Current_A: 6.3A; CT: False; Green_Lifecycle: Active; Row_Count: 1; CNHeader: True
J8 = CMP-0075082-1: Connector, Receptacle, Micro-USB Type AB, R/A, Bottom Mount SMT; Manufacturer: Hirose Electric Co. Ltd.; CNHeader: False; Green_Lifecycle: Not Set; Gender: Female; Green_REACh: Incomplete; CompType: USB; CT: True
J10 = CMP-0055856-1: Connector, RJ45 with integrated magnetics, 1x1, Gold, R/A, TH; Manufacturer: Pulse Engineering; CNHeader: FALSE; Green_Lifecycle: Not Set; Green_REACh: Incomplete; CT: TRUE
JP4-JP7 = CMP-0075500-1: as JP1 on sheet MCU051A_Power_JTAG
R1 = CMP-0025925-3: RES, 47 k, 5%, 0.1 W, 0603; Manufacturer: Yageo America; Power_W: 100mW; TempCo: 100 ppm/C; Value_Code: 47k0; U/M: EA; Value: 47k; EIA_Code: E24; SizeX_mm: 1.6; SizeY_mm: 0.8; SizeZ_mm: 1; Value2: 0.1W; SizeArea_mm2: 1.28; VDC_V: 50V; AEC Category: Q200
R2 = CMP-0025825-4: RES, 51, 5%, 0.1 W, AEC-Q200 Grade 0, 0603; Manufacturer: Vishay-Dale; Power_W: 100mW; TempCo: 200 ppm/C; Value_Code: 51R0; Value: 51; EIA_Code: E24; SizeX_mm: 1.6; SizeY_mm: 0.8; SizeZ_mm: 1; Value2: 0.1W; SizeArea_mm2: 1.28; AEC Qualified: Y; VDC_V: 75V; AEC Category: Q200; AEC Grade: 0
R3 = CMP-0020445-3: RES, 100, 5%, 0.125 W, AEC-Q200 Grade 0, 0805; Manufacturer: Vishay-Dale; Power_W: 125mW; TempCo: 200 ppm/C; Value_Code: 100R; Value: 100; EIA_Code: E24; SizeX_mm: 2; SizeY_mm: 1.25; SizeZ_mm: 1.45; Value2: 0.125W; SizeArea_mm2: 2.5; AEC Qualified: Y; VDC_V: 150V; AEC Category: Q200; AEC Grade: 0
R4 R32 R33 = CMP-0020446-3: RES, 10 k, 5%, 0.125 W, AEC-Q200 Grade 0, 0805; Manufacturer: Vishay-Dale; Power_W: 125mW; TempCo: 200 ppm/C; Value_Code: 10k0; Value: 10k; EIA_Code: E24; SizeX_mm: 2; SizeY_mm: 1.25; SizeZ_mm: 1.45; Value2: 0.125W; SizeArea_mm2: 2.5; CompType: Resistor; AEC Qualified: Y; VDC_V: 150V; AEC Category: Q200; AEC Grade: 0
R5 R14 = CMP-0025736-4: RES, 1.0 M, 5%, 0.1 W, AEC-Q200 Grade 0, 0603; Manufacturer: Vishay-Dale; Power_W: 100mW; TempCo: 200 ppm/C; Value_Code: 1M00; Value: 1.0Meg; EIA_Code: E24; Res_ohm: 1M; SizeX_mm: 1.6; SizeY_mm: 0.8; SizeZ_mm: 1; Value2: 0.1W; SizeArea_mm2: 1.28; AEC Qualified: Y; VDC_V: 75V; AEC Category: Q200; AEC Grade: 0
R6 = CMP-0023154-3: RES, 4.87 k, 1%, 0.1 W, 0603; Manufacturer: Yageo America; Power_W: 100mW; TempCo: 200 ppm/C; Value_Code: 4k87; U/M: EA; Value: 4.87k; EIA_Code: E96; SizeX_mm: 1.6; SizeY_mm: 0.8; SizeZ_mm: 1; Value2: 0.1W; SizeArea_mm2: 1.28; CompType: Resistor; VDC_V: 150V; AEC Category: Q200
R8 R9 R12 R13 = CMP-0023143-3: RES, 49.9, 1%, 0.1 W, 0603; Manufacturer: Yageo America; Power_W: 100mW; TempCo: 200 ppm/C; Value_Code: 49R9; U/M: EA; Value: 49.9; EIA_Code: E96; SizeX_mm: 1.6; SizeY_mm: 0.8; SizeZ_mm: 1; Value2: 0.1W; SizeArea_mm2: 1.28; VDC_V: 150V; AEC Category: Q200
R16 R23 = CMP-0025912-3: RES, 330, 5%, 0.1 W, 0603; Manufacturer: Yageo America; Power_W: 100mW; TempCo: 100 ppm/C; Value_Code: 330R; U/M: EA; Value: 330; EIA_Code: E24; SizeX_mm: 1.6; SizeY_mm: 0.8; SizeZ_mm: 1; Value2: 0.1W; SizeArea_mm2: 1.28; VDC_V: 50V; AEC Category: Q200
R26-R29 = CMP-0025697-4: RES, 0, 5%, 0.1 W, AEC-Q200 Grade 0, 0603; Manufacturer: Vishay-Dale; Power_W: 100mW; TempCo: 200 ppm/C; Value_Code: 0000; Value: 0; EIA_Code: E24; SizeX_mm: 1.6; SizeY_mm: 0.8; SizeZ_mm: 1; Value2: 0.1W; SizeArea_mm2: 1.28; AEC Qualified: Y; VDC_V: 75V; AEC Category: Q200
R30 = CMP-0025700-4: RES, 100, 5%, 0.1 W, AEC-Q200 Grade 0, 0603; Manufacturer: Vishay-Dale; Power_W: 100mW; TempCo: 200 ppm/C; Value_Code: 100R; Value: 100; EIA_Code: E24; SizeX_mm: 1.6; SizeY_mm: 0.8; SizeZ_mm: 1; Value2: 0.1W; SizeArea_mm2: 1.28; AEC Qualified: Y; VDC_V: 75V; AEC Category: Q200; AEC Grade: 0
R31 = CMP-0025913-3: RES, 33 k, 5%, 0.1 W, 0603; Manufacturer: Yageo America; Power_W: 100mW; TempCo: 100 ppm/C; Value_Code: 33k0; U/M: EA; Value: 33k; EIA_Code: E24; SizeX_mm: 1.6; SizeY_mm: 0.8; SizeZ_mm: 1; Value2: 0.1W; SizeArea_mm2: 1.28; VDC_V: 50V; AEC Category: Q200
SW1 SW2 SW7 = CMP-0074594-1: Switch, SPST-NO, Off-Mom, 0.02 A, 15 VDC, TH; Manufacturer: Panasonic; CurrentRating_mA: 20A; Green_Lifecycle: Not Set; SizeAreaWB_mm2: 64.0; Green_REACh: Incomplete; PositionCount: 1.0; SizeZ_mm: 4.5; SizeX_mm: 6.0; SizeArea_mm2: 36.0; VDC_V: 15V
U1 = CMP-0077957-1: MSP432E411YTZAD, ZAD0212A (NFBGA-212); Alternate PartNumber: MSP432E411YTZADR; Alternate Manufacturer: Texas Instruments; SizeAreaWB_mm2: 144; SizeZ_mm: 1; SizeX_mm: 10; SizeArea_mm2: 100; CompType: IC; AEC Qualified: N; AEC Category: Q200
U3 = CMP-0074276-1: Single, Current-Limited, Power-Distribution Switch, DBV0005A (SOT-23-5); Alternate PartNumber: TPS2051BDBVT; Alternate Manufacturer: Texas Instruments; Green_Lifecycle: Active; SizeAreaWB_mm2: 14.82; Green_REACh: Passed; U/M: EA; SizeZ_mm: 1.45; SizeX_mm: 2.8; SizeY_mm: 2.9; SizeArea_mm2: 8.12; CompType: IC
U4 = CMP-0043122-2: USB ESD Solution with Power Clamp, 4 Channels, -40 to +85 degC, 6-pin SON (DRY), Green (RoHS & no Sb/Br); Manufacturer: Texas Instruments; IO Leakage Current(nA): 10; USB High Speed: TRUE; Breakdown Voltage(Min)(V): 6; IO Capacitance(Typ)(pF): 0.8; AEC Category: Q200; AEC Qualified: N; CompType: IC; SizeAreaWB_mm2: 4.9; SizeArea_mm2: 1.45; SizeX_mm: 1.0; SizeZ_mm: 0.6
Y1 = CMP-0004652-3: Crystal, 25 MHz, 8pF, SMD; Manufacturer: Fox; TaMax_C: 85°C; TaMin_C: -40°C; Frequency Stability: +/-20ppm; Frequency_Fixed: 25MHz
Y2 = CMP-0004653-5: Crystal, 32.768 kHz,  SMD; Manufacturer: Citizen FineDevice; TaMin_C: -40°C; Frequency Stability: +/-20ppm; TaMax_C: 85°C; AEC Category: Q200; AEC Qualified: N

## Sheet MCU051A_LCD_Memory.SchDoc
size 431 x 279 mm; Date: Not shown in title block; ApprovedBy: Not shown in title block; CheckedBy: Not shown in title block; Author: Not shown in title block; CompanyName: Not shown in title block; Engineer: Not shown in title block; Organization: Not shown in title block; Address1: Not shown in title block; Address2: Not shown in title block; Address3: Not shown in title block; Address4: Not shown in title block; DocumentNumber: 1; Revision: Use project parameter SCH_Rev; SheetNumber: 3; SheetTotal: 4; PageSetup: Record=PageOptions¦CenterHorizontal=True¦CenterVertical=True¦PrintScale=1.00¦XCorrection=1.00¦YCorrection=1.00¦PrintKind=0¦BorderSize=5000000¦LeftOffset=0¦BottomOffset=0¦Orientation=2¦PaperLength=1000¦PaperWidth=1000¦Scale=100¦PaperSource=15¦PrintQuality=600¦MediaType=1¦DitherType=10¦PaperKind=Letter¦PrintScaleMode=1
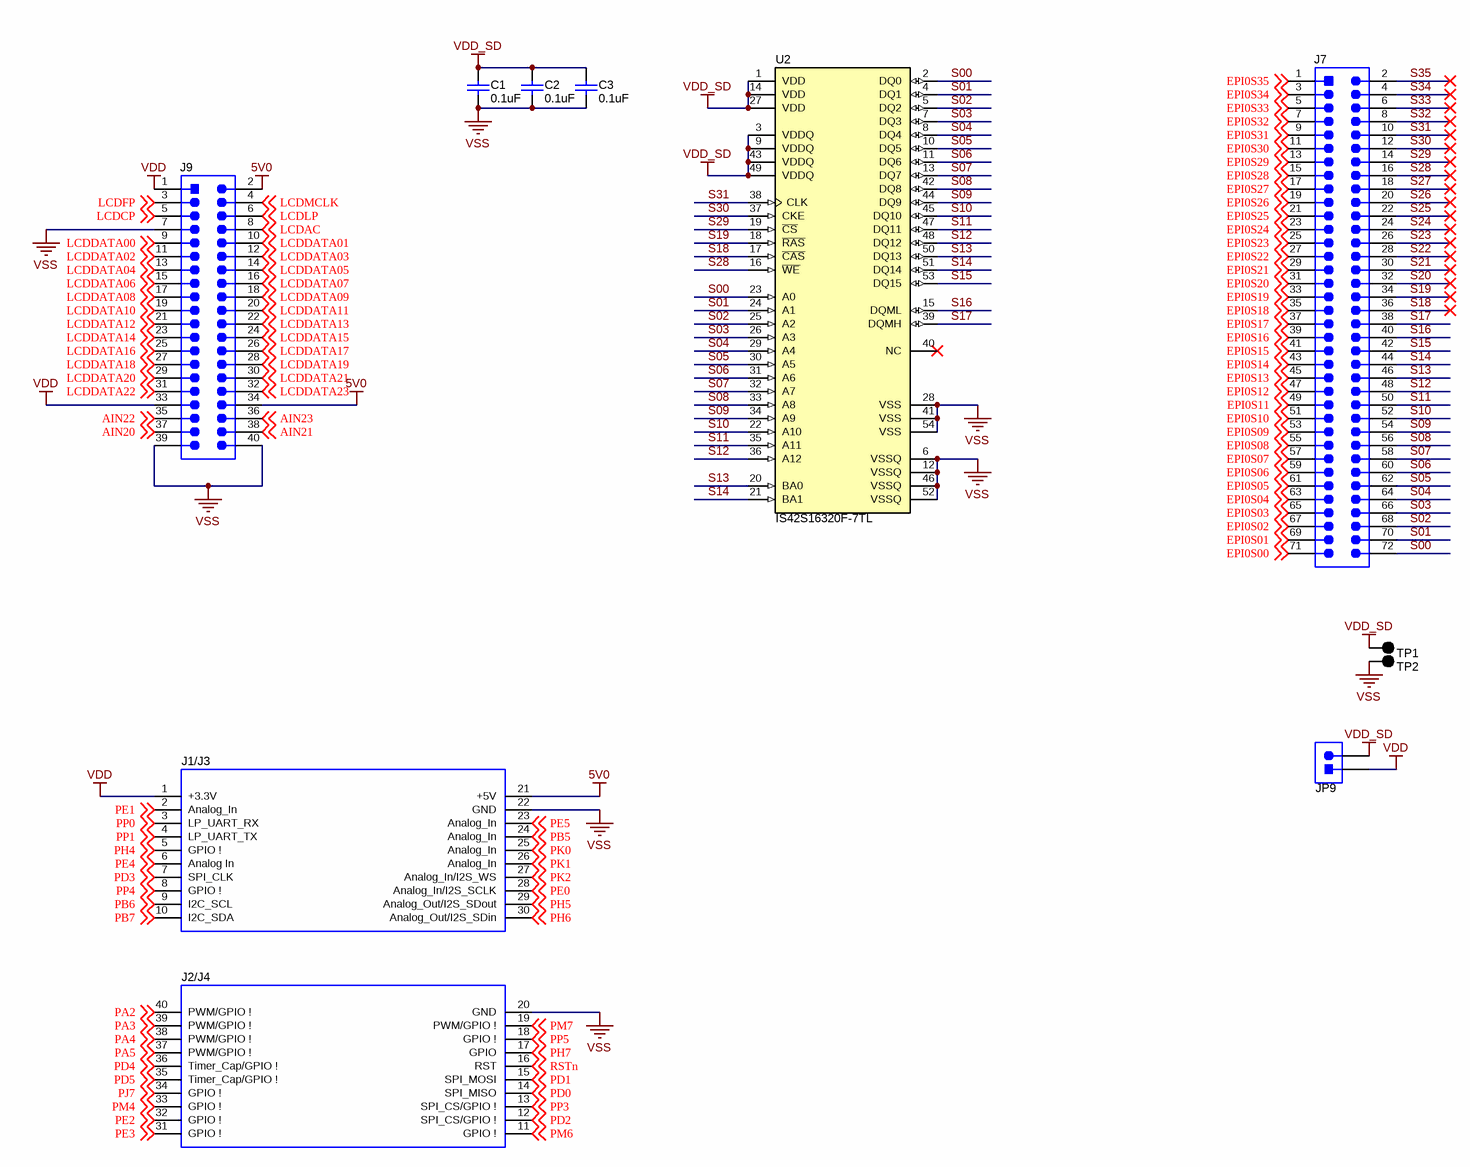
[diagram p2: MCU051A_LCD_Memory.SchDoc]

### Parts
C1  ValueDisplayed: 0.1uF  [0402]  (hidden comment: GRM155R71A104KA01D)
C2  ValueDisplayed: 0.1uF  [0402]  (hidden comment: GRM155R71A104KA01D)
C3  ValueDisplayed: 0.1uF  [0402]  (hidden comment: GRM155R71A104KA01D)
J1/J3  SSQ-110-03-T-D  [BoosterPack_40pin_J1J3]  (value not drawn)
J2/J4  SSQ-110-03-T-D  [BoosterPack_40pin_J2J4]  (value not drawn)
J7  TSW-136-07-G-D  [Samtec_TSW-136-07-x-D]  (value not drawn)
J9  TSW-120-07-G-D  [TSW-120-07-G-D]  (value not drawn)
JP9  HMTSW-102-07-G-S-240  [SAMTEC_HMTSW-102-07-G-S-240]  (value not drawn)
TP1  5001  [Keystone5001]  (value not drawn)
TP2  5001  [Keystone5001]  (value not drawn)
U2  IS42S16320F-7TL  [TSOP-2_54]

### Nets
5V0: J1/J3.21(+5V) J9.2 J9.34
VDD: J1/J3.1(+3.3V) J9.1 J9.33 JP9.1
VDD_SD: C1.2 C2.2 C3.2 JP9.2 TP1.1 U2.1(VDD) U2.3(VDDQ) U2.9(VDDQ) U2.14(VDD) U2.27(VDD) U2.43(VDDQ) U2.49(VDDQ)
VSS: C1.1 C2.1 C3.1 J1/J3.22(GND) J2/J4.20(GND) J9.7 J9.39 J9.40 TP2.1 U2.6(VSSQ) U2.12(VSSQ) U2.28(VSS) U2.41(VSS) U2.46(VSSQ) U2.52(VSSQ) U2.54(VSS)
AIN20: J9.37 ; off-sheet AIN20  [project net PE6]
AIN21: J9.38 ; off-sheet AIN21  [project net PE7]
AIN22: J9.35 ; off-sheet AIN22  [project net PP7]
AIN23: J9.36 ; off-sheet AIN23  [project net PP6]
EPI0S00: J7.71 ; off-sheet EPI0S00  [project net PH0]
EPI0S01: J7.69 ; off-sheet EPI0S01  [project net PH1]
EPI0S02: J7.67 ; off-sheet EPI0S02  [project net PH2]
EPI0S03: J7.65 ; off-sheet EPI0S03  [project net PK3]
EPI0S04: J7.63 ; off-sheet EPI0S04  [project net PC7]
EPI0S05: J7.61 ; off-sheet EPI0S05  [project net PC6]
EPI0S06: J7.59 ; off-sheet EPI0S06  [project net PC5]
EPI0S07: J7.57 ; off-sheet EPI0S07  [project net PC4]
EPI0S08: J7.55 ; off-sheet EPI0S08  [project net PA6]
EPI0S09: J7.53 ; off-sheet EPI0S09  [project net PA7]
EPI0S10: J7.51 ; off-sheet EPI0S10  [project net PG1]
EPI0S11: J7.49 ; off-sheet EPI0S11  [project net PG0]
EPI0S12: J7.47 ; off-sheet EPI0S12  [project net PM3]
EPI0S13: J7.45 ; off-sheet EPI0S13  [project net PM2]
EPI0S14: J7.43 ; off-sheet EPI0S14  [project net PM1]
EPI0S15: J7.41 ; off-sheet EPI0S15  [project net PM0]
EPI0S16: J7.39 ; off-sheet EPI0S16  [project net PL0]
EPI0S17: J7.37 ; off-sheet EPI0S17  [project net PL1]
EPI0S18: J7.35 ; off-sheet EPI0S18  [project net PL2]
EPI0S19: J7.33 ; off-sheet EPI0S19  [project net PL3]
EPI0S20: J7.31 ; off-sheet EPI0S20  [project net PQ0]
EPI0S21: J7.29 ; off-sheet EPI0S21  [project net PQ1]
EPI0S22: J7.27 ; off-sheet EPI0S22  [project net PQ2]
EPI0S23: J7.25 ; off-sheet EPI0S23  [project net PQ3]
EPI0S24: J7.23 ; off-sheet EPI0S24  [project net PK7]
EPI0S25: J7.21 ; off-sheet EPI0S25  [project net PK6]
EPI0S26: J7.19 ; off-sheet EPI0S26  [project net PL4]
EPI0S27: J7.17 ; off-sheet EPI0S27  [project net PB2]
EPI0S28: J7.15 ; off-sheet EPI0S28  [project net PB3]
EPI0S29: J7.13 ; off-sheet EPI0S29  [project net PP2]
EPI0S30: J7.11 ; off-sheet EPI0S30  [project net PN3]
EPI0S31: J7.9 ; off-sheet EPI0S31  [project net PK5]
EPI0S32: J7.7 ; off-sheet EPI0S32  [project net PK4]
EPI0S33: J7.5 ; off-sheet EPI0S33  [project net PL5]
EPI0S34: J7.3 ; off-sheet EPI0S34  [project net PN4]
EPI0S35: J7.1 ; off-sheet EPI0S35  [project net PN5]
LCDAC: J9.8 ; off-sheet LCDAC  [project net PJ6]
LCDCP: J9.5 ; off-sheet LCDCP  [project net PR0]
LCDDATA00: J9.9 ; off-sheet LCDDATA00  [project net PR4]
LCDDATA01: J9.10 ; off-sheet LCDDATA01  [project net PR5]
LCDDATA02: J9.11 ; off-sheet LCDDATA02  [project net PF7]
LCDDATA03: J9.12 ; off-sheet LCDDATA03  [project net PR3]
LCDDATA04: J9.13 ; off-sheet LCDDATA04  [project net PR6]
LCDDATA05: J9.14 ; off-sheet LCDDATA05  [project net PR7]
LCDDATA06: J9.15 ; off-sheet LCDDATA06  [project net PS4]
LCDDATA07: J9.16 ; off-sheet LCDDATA07  [project net PS5]
LCDDATA08: J9.17 ; off-sheet LCDDATA08  [project net PS6]
LCDDATA09: J9.18 ; off-sheet LCDDATA09  [project net PS7]
LCDDATA10: J9.19 ; off-sheet LCDDATA10  [project net PT0]
LCDDATA11: J9.20 ; off-sheet LCDDATA11  [project net PT1]
LCDDATA12: J9.21 ; off-sheet LCDDATA12  [project net PN7]
LCDDATA13: J9.22 ; off-sheet LCDDATA13  [project net PN6]
LCDDATA14: J9.23 ; off-sheet LCDDATA14  [project net PJ2]
LCDDATA15: J9.24 ; off-sheet LCDDATA15  [project net PJ3]
LCDDATA16: J9.25 ; off-sheet LCDDATA16  [project net PJ4]
LCDDATA17: J9.26 ; off-sheet LCDDATA17  [project net PJ5]
LCDDATA18: J9.27 ; off-sheet LCDDATA18  [project net PT2]
LCDDATA19: J9.28 ; off-sheet LCDDATA19  [project net PT3]
LCDDATA20: J9.29 ; off-sheet LCDDATA20  [project net PS0]
LCDDATA21: J9.30 ; off-sheet LCDDATA21  [project net PS1]
LCDDATA22: J9.31 ; off-sheet LCDDATA22  [project net PB4]
LCDDATA23: J9.32 ; off-sheet LCDDATA23  [project net PS3]
LCDFP: J9.3 ; off-sheet LCDFP  [project net PR1]
LCDLP: J9.6 ; off-sheet LCDLP  [project net PR2]
LCDMCLK: J9.4 ; off-sheet LCDMCLK  [project net PF6]
PA2: J2/J4.40(PWM/GPIO_!) ; off-sheet PA2
PA3: J2/J4.39(PWM/GPIO_!) ; off-sheet PA3
PA4: J2/J4.38(PWM/GPIO_!) ; off-sheet PA4
PA5: J2/J4.37(PWM/GPIO_!) ; off-sheet PA5
PB5: J1/J3.24(Analog_In) ; off-sheet PB5
PB6: J1/J3.9(I2C_SCL) ; off-sheet PB6
PB7: J1/J3.10(I2C_SDA) ; off-sheet PB7
PD0: J2/J4.14(SPI_MISO) ; off-sheet PD0
PD1: J2/J4.15(SPI_MOSI) ; off-sheet PD1
PD2: J2/J4.12(SPI_CS/GPIO_!) ; off-sheet PD2
PD3: J1/J3.7(SPI_CLK) ; off-sheet PD3
PD4: J2/J4.36(Timer_Cap/GPIO_!) ; off-sheet PD4
PD5: J2/J4.35(Timer_Cap/GPIO_!) ; off-sheet PD5
PE0: J1/J3.28(Analog_In/I2S_SCLK) ; off-sheet PE0
PE1: J1/J3.2(Analog_In) ; off-sheet PE1
PE2: J2/J4.32(GPIO_!) ; off-sheet PE2
PE3: J2/J4.31(GPIO_!) ; off-sheet PE3
PE4: J1/J3.6(Analog_In) ; off-sheet PE4
PE5: J1/J3.23(Analog_In) ; off-sheet PE5
PH4: J1/J3.5(GPIO_!) ; off-sheet PH4
PH5: J1/J3.29(Analog_Out/I2S_SDout) ; off-sheet PH5
PH6: J1/J3.30(Analog_Out/I2S_SDin) ; off-sheet PH6
PH7: J2/J4.17(GPIO) ; off-sheet PH7
PJ7: J2/J4.34(GPIO_!) ; off-sheet PJ7
PK0: J1/J3.25(Analog_In) ; off-sheet PK0
PK1: J1/J3.26(Analog_In) ; off-sheet PK1
PK2: J1/J3.27(Analog_In/I2S_WS) ; off-sheet PK2
PM4: J2/J4.33(GPIO_!) ; off-sheet PM4
PM6: J2/J4.11(GPIO_!) ; off-sheet PM6
PM7: J2/J4.19(PWM/GPIO_!) ; off-sheet PM7
PP0: J1/J3.3(LP_UART_RX) ; off-sheet PP0
PP1: J1/J3.4(LP_UART_TX) ; off-sheet PP1
PP3: J2/J4.13(SPI_CS/GPIO_!) ; off-sheet PP3
PP4: J1/J3.8(GPIO_!) ; off-sheet PP4
PP5: J2/J4.18(GPIO_!) ; off-sheet PP5
RSTn: J2/J4.16(RST) ; off-sheet RSTn
S00: J7.72 U2.2(DQ0) U2.23(A0)
S01: J7.70 U2.4(DQ1) U2.24(A1)
S02: J7.68 U2.5(DQ2) U2.25(A2)
S03: J7.66 U2.7(DQ3) U2.26(A3)
S04: J7.64 U2.8(DQ4) U2.29(A4)
S05: J7.62 U2.10(DQ5) U2.30(A5)
S06: J7.60 U2.11(DQ6) U2.31(A6)
S07: J7.58 U2.13(DQ7) U2.32(A7)
S08: J7.56 U2.33(A8) U2.42(DQ8)
S09: J7.54 U2.34(A9) U2.44(DQ9)
S10: J7.52 U2.22(A10) U2.45(DQ10)
S11: J7.50 U2.35(A11) U2.47(DQ11)
S12: J7.48 U2.36(A12) U2.48(DQ12)
S13: J7.46 U2.20(BA0) U2.50(DQ13)
S14: J7.44 U2.21(BA1) U2.51(DQ14)
S15: J7.42 U2.53(DQ15)
S16: J7.40 U2.15(DQML)
S17: J7.38 U2.39(DQMH)
S18: J7.36 U2.17(~{CAS})
S19: J7.34 U2.18(~{RAS})
S20: J7.32
S21: J7.30
S22: J7.28
S23: J7.26
S24: J7.24
S25: J7.22
S26: J7.20
S27: J7.18
S28: J7.16 U2.16(~{WE})
S29: J7.14 U2.19(~{CS})
S30: J7.12 U2.37(CKE)
S31: J7.10 U2.38(CLK)
S32: J7.8
S33: J7.6
S34: J7.4
S35: J7.2

Not connected (* = marked no-connect by the designer): U2 40(NC)*

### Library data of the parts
C1-C3 = CMP-0006629-2: as C14 on sheet MCU051A_MSP432E_Device
J1/J3 = CMP-0003837-2: Receptacle, 2.54mm, 10x2, Tin, TH; Alternate PartNumber: CRD-081413-A-G; Manufacturer: Samtec; Alternate Manufacturer: Major League Electronics; Note: Booster Pack 40 pin J1 and J3; Green_Lifecycle: Active; Green_REACh: Incomplete
J2/J4 = CMP-0078266-2: Receptacle, 2.54mm, 10x2, Tin, TH; Alternate PartNumber: CRD-081413-A-G; Manufacturer: Samtec; Alternate Manufacturer: Major League Electronics; Note: Booster Pack 40 pin J2 and J4; Green_REACh: Incomplete; Green_Lifecycle: Active
J7 = CMP-0080465-1: Header, 2.54mm, 36x2, Gold, TH; Manufacturer: Samtec; Pitch_mm: 2.54; Gender: Male; Cert_UL: Y; Shrouded: N; Row_Count: 2
J9 = CMP-0075433-1: as J5 on sheet MCU051A_MSP432E_Device
JP9 = CMP-0075500-1: as JP1 on sheet MCU051A_Power_JTAG
TP1 TP2 = CMP-0055138-1: as TP3 on sheet MCU051A_Power_JTAG
U2 = CMP-0004972-1: 32Mx16 512Mb SDRAM, TSOP-2_54; Manufacturer: Integrated Silicon Solution Inc.; SizeAreaWB_mm2: 333.2672; SizeZ_mm: 1.2; SizeX_mm: 11.76; SizeY_mm: 22.22; SizeArea_mm2: 261.3072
